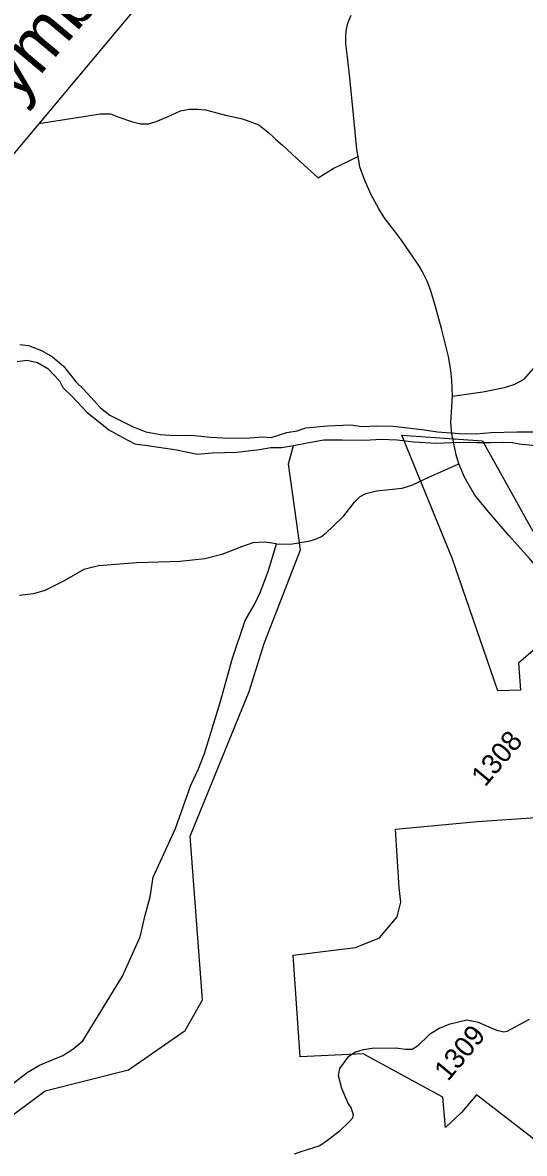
# Model space of a CAD drawing. Extents: x 555292 to 2368606, y 503623 to 1171444.
# Drawn here: x 2356645 to 2357011, y 1163265 to 1164090 of the extents above; entities that cross this region are included whole.
import ezdxf

# ---------------------------------------------------------------- set-up
doc = ezdxf.new("R2010")
doc.units = 0
for name, color, linetype in [('Old_Level_1', 7, 'Continuous'), ('Old_Level_32', 7, 'Continuous'), ('Old_Level_48', 7, 'Continuous'), ('Old_Level_59', 7, 'Continuous'), ('Old_Level_60', 7, 'Continuous'), ('Old_Level_8', 7, 'Continuous'), ('Sheet Title CELL', 7, 'Continuous')]:
    doc.layers.add(name, color=color, linetype=linetype)

msp = doc.modelspace()

# ---------------------------------------------------------------- linework, layer by layer
at = {"layer": 'Old_Level_1'}
msp.add_line((2357074.86, 1164516.36), (2356126.11, 1163382.09), dxfattribs=at)
at = {"layer": 'Old_Level_32'}
for points in [[(2356889.4, 1163992.05), (2356888.28, 1163997.17), (2356885.92, 1164022.5), (2356883.19, 1164049.61), (2356881.58, 1164064.66), (2356880.35, 1164074.29), (2356880.33, 1164080.62), (2356880.75, 1164084.95), (2356881.7, 1164089.34), (2356884.14, 1164095.2)], [(2356656.51, 1164016.2), (2356701.45, 1164023.24), (2356708.84, 1164023.23), (2356714.93, 1164020.86), (2356724.87, 1164017.56), (2356730.77, 1164016.07), (2356736.42, 1164016.03), (2356742.18, 1164017.7), (2356750.38, 1164021.02), (2356759.92, 1164025.47)], [(2356759.92, 1164025.47), (2356766.16, 1164026.6), (2356772.48, 1164026.73), (2356778.08, 1164026.14), (2356792.61, 1164022.32), (2356804.99, 1164019.74), (2356816.91, 1164015.24)], [(2356816.91, 1164015.24), (2356824.23, 1164009.4), (2356827.48, 1164006.42), (2356829.15, 1164004.93), (2356834.29, 1164000.35), (2356844.64, 1163990.59), (2356860.23, 1163976.65)], [(2356860.23, 1163976.65), (2356871.23, 1163983.47), (2356889.4, 1163992.05)], [(2356918.13, 1163934.91), (2356908.34, 1163947.77), (2356904.29, 1163954.5), (2356899.13, 1163963.82), (2356894.27, 1163974.64), (2356890.5, 1163984.67), (2356889.4, 1163992.05)], [(2356949.99, 1163866.63), (2356945.43, 1163883.38), (2356942.33, 1163894.09), (2356939.54, 1163901.32), (2356935.91, 1163908.51), (2356933.52, 1163912.73), (2356929.82, 1163918.04), (2356920.93, 1163931.09), (2356918.13, 1163934.91)], [(2356958.09, 1163817.28), (2356957.61, 1163828.9), (2356957.02, 1163836.2), (2356955.25, 1163846.28), (2356949.99, 1163866.63)], [(2356958.09, 1163817.28), (2356980.29, 1163820.55), (2356995.94, 1163823.58), (2357003.46, 1163826), (2357010.27, 1163829.86), (2357020.96, 1163841.81)], [(2356957.63, 1163789.97), (2356956.89, 1163798.23), (2356958.09, 1163817.28)], [(2356962.82, 1163768.06), (2356960.89, 1163774.59), (2356957.63, 1163789.97)], [(2356829.83, 1163709.54), (2356840.11, 1163709.35), (2356854.4, 1163711.89), (2356859.5, 1163713.46), (2356862.54, 1163715), (2356866.2, 1163717.86), (2356870.64, 1163722.12), (2356878.99, 1163730.01), (2356886.73, 1163739.97), (2356890.69, 1163744.05), (2356895.04, 1163746.34), (2356902.65, 1163748.34), (2356921.43, 1163750.32), (2356928.43, 1163752.53), (2356940.89, 1163758.35), (2356962.82, 1163768.06)], [(2357027.41, 1163637.86), (2357024.66, 1163644.64), (2357024, 1163648.71), (2357022.83, 1163671.56), (2357021.77, 1163685.93), (2357020.57, 1163689.92), (2357019.6, 1163691.69), (2357018.03, 1163694.38), (2357014.25, 1163699), (2356999.45, 1163715.44), (2356984.6, 1163732.76), (2356974.38, 1163745.25), (2356966.9, 1163758.3), (2356962.82, 1163768.06)], [(2356616.04, 1163299.14), (2356648.13, 1163323.99), (2356657.11, 1163329.48), (2356674.1, 1163336.52), (2356681.48, 1163341.03), (2356688.58, 1163347.24), (2356717.65, 1163394.38), (2356730.44, 1163422.91), (2356734.04, 1163438.87), (2356737.65, 1163452.15), (2356740.01, 1163466.47), (2356756.16, 1163502.05), (2356767.35, 1163533.68), (2356772.92, 1163545.46), (2356777.46, 1163556.63), (2356788.82, 1163594.02), (2356797.73, 1163626.25), (2356806.97, 1163653.61), (2356814.1, 1163665.81), (2356818.12, 1163674.61), (2356824.31, 1163690.8), (2356829.83, 1163709.54)], [(2356829.83, 1163709.54), (2356821.26, 1163710.97), (2356812.66, 1163710.28), (2356804.32, 1163707.5), (2356789.91, 1163701.78), (2356777.61, 1163698.58), (2356759.53, 1163696.65), (2356728.03, 1163695.75), (2356700.02, 1163693.52), (2356689.47, 1163690.99), (2356675.09, 1163682.58), (2356661.04, 1163675.69), (2356652.75, 1163673.14), (2356642.6, 1163671.87)], [(2357013.9, 1163362.68), (2356997.69, 1163354.05), (2356995.6, 1163353.48), (2356990.34, 1163354.55), (2356977.06, 1163360.51), (2356968.67, 1163362.08), (2356955.44, 1163359.12), (2356948.45, 1163356.19), (2356941.32, 1163351.77), (2356932.67, 1163343.17), (2356928.71, 1163340.92), (2356923.83, 1163340.87), (2356916.81, 1163341.7), (2356899.56, 1163341.6), (2356893.01, 1163340.52), (2356887.34, 1163338.81), (2356881.83, 1163335.25), (2356875.69, 1163327.06), (2356874.66, 1163321.72), (2356877.24, 1163312.5), (2356882.15, 1163301.23), (2356884.28, 1163297.94), (2356885.81, 1163293.13), (2356885.21, 1163290.6), (2356882.69, 1163288.07), (2356875.61, 1163281.09), (2356867.08, 1163274.49), (2356861.4, 1163270.65), (2356846.94, 1163265.91), (2356842.68, 1163264.38)]]:
    msp.add_lwpolyline(points, dxfattribs=at)
at = {"layer": 'Old_Level_48'}
for points in [[(2357018.67, 1163633.24), (2357006.19, 1163622.67), (2357007.57, 1163602.85), (2356991.09, 1163602.31), (2356957.97, 1163699.25), (2356921.09, 1163788.94), (2356980.03, 1163784.72), (2357016.63, 1163718.76)], [(2356975.51, 1163307.76), (2356964.73, 1163294.87), (2356953.07, 1163283.96), (2356951.07, 1163306.14), (2356892.98, 1163337.71), (2356847.14, 1163335.42), (2356842, 1163409.52), (2356887.37, 1163415.24), (2356905, 1163422.33), (2356917.66, 1163437.47), (2356920.51, 1163448.34), (2356919.15, 1163458.84), (2356916.61, 1163501.52), (2356976.33, 1163507.03), (2357018.94, 1163509.97)], [(2357046.04, 1163253.33), (2356975.51, 1163307.76)]]:
    msp.add_lwpolyline(points, dxfattribs=at)
at = {"layer": 'Old_Level_59'}
msp.add_lwpolyline([(2356500.04, 1163069.31), (2356537.53, 1163135.69), (2356558.05, 1163163.23), (2356627.54, 1163280.41), (2356639.35, 1163294.45), (2356661.2, 1163310.55), (2356721.99, 1163325.89), (2356763.21, 1163354.73), (2356775.76, 1163377.12), (2356766.96, 1163496.3), (2356809.79, 1163601.84), (2356820.83, 1163636.97), (2356847.39, 1163705.37), (2356838.47, 1163768.01), (2356842.31, 1163781.37)], dxfattribs=at)
at = {"layer": 'Old_Level_60'}
for points in [[(2356642.82, 1163855.14), (2356649.01, 1163854.27), (2356658.42, 1163850.68), (2356666.65, 1163846.16), (2356674.46, 1163839.35), (2356683.69, 1163827.57), (2356689.17, 1163822.49), (2356694.38, 1163816.69), (2356701.55, 1163808.74), (2356708.28, 1163803.49), (2356724.91, 1163795.22), (2356734.64, 1163791.22), (2356745.25, 1163789.41), (2356755.46, 1163788.56), (2356767.55, 1163788.85), (2356781.72, 1163787.34), (2356790.66, 1163787.02), (2356800.17, 1163786.74), (2356810.4, 1163786.91), (2356819.85, 1163787.77), (2356825.88, 1163787.3), (2356831.18, 1163788.99), (2356837.41, 1163790.95), (2356844.8, 1163792.04), (2356851.16, 1163794.15), (2356867.11, 1163795.69), (2356883.89, 1163796.38), (2356892.01, 1163795.31), (2356902.73, 1163795.63), (2356914.67, 1163795.38), (2356921.21, 1163794.66), (2356935.74, 1163792.93), (2356947.18, 1163791.29)], [(2356640.84, 1163842.69), (2356648.05, 1163843.58), (2356655.71, 1163841.99), (2356663.17, 1163837.58), (2356671.55, 1163828.62), (2356674.13, 1163823.59), (2356680.93, 1163817.02), (2356691.84, 1163805.38), (2356699.86, 1163799.21), (2356707.6, 1163792.73), (2356717.31, 1163787.49), (2356726.66, 1163782.65), (2356735.64, 1163781.38), (2356755.69, 1163778.44), (2356765.1, 1163776.46), (2356772.16, 1163774.97), (2356782.9, 1163775.91), (2356800.94, 1163776.46), (2356817.35, 1163778.51), (2356825.6, 1163779.8), (2356833.38, 1163779.94), (2356842.31, 1163781.37)], [(2356947.18, 1163791.29), (2356963.25, 1163790.21), (2356975.18, 1163789.8)], [(2356975.18, 1163789.8), (2356986.37, 1163790.75), (2357005.06, 1163791.27), (2357019.97, 1163791.41)], [(2356842.31, 1163781.37), (2356852.24, 1163783.21), (2356864.43, 1163785.42), (2356877.72, 1163785.49), (2356894.21, 1163785.26), (2356906.05, 1163786.07), (2356917.86, 1163785.44), (2356929.93, 1163784.08), (2356946.49, 1163783.15), (2356963.48, 1163783.75), (2356975.49, 1163783.53), (2356985.62, 1163783.62), (2356995.51, 1163783.79), (2357001.72, 1163783.46), (2357009.71, 1163782.04)], [(2357018.35, 1163781.16), (2357009.71, 1163782.04)]]:
    msp.add_lwpolyline(points, dxfattribs=at)

# ---------------------------------------------------------------- texts
at = {"layer": 'Old_Level_8'}
for s, p in [('1308', (2356981.86, 1163531.74)), ('1309', (2356954.82, 1163317.04))]:
    msp.add_text(s, height=14.764, rotation=50.08952, dxfattribs=at).set_placement(p)
at = {"layer": 'Sheet Title CELL'}
msp.add_text('See Sheet 1B For Conventional Symbols', height=37.4996, rotation=50.08952, dxfattribs=at).set_placement((2356157.95, 1163453.74))

doc.saveas('drawing.dxf')
